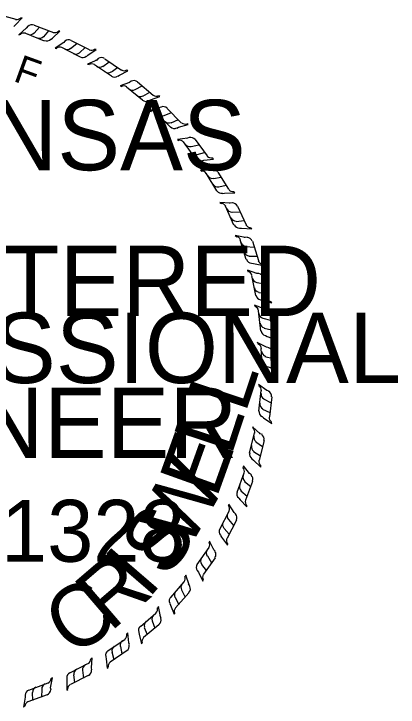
# Model space of a CAD drawing. Extents: x 208.7 to 242.8, y 328.9 to 350.7.
# Drawn here: x 234.537 to 235.56, y 330.334 to 332.182 of the extents above; entities that cross this region are included whole.
import ezdxf

# ---------------------------------------------------------------- set-up
doc = ezdxf.new("R2010")
doc.units = 0
doc.layers.add('Border 2660-Hwy18 - Stamp-ChrisC', color=7, linetype='Continuous')

msp = doc.modelspace()

# ---------------------------------------------------------------- linework, layer by layer
at = {"layer": 'Border 2660-Hwy18 - Stamp-ChrisC'}
for p, q in [((234.4894, 332.1816), (234.5419, 332.1674)), ((234.5404, 332.1516), (234.5584, 332.1711)), ((234.5584, 332.1711), (234.5554, 332.1704)), ((234.5367, 332.1479), (234.5404, 332.1516)), ((234.5734, 332.1486), (234.5704, 332.1441)), ((234.5907, 332.1516), (234.6417, 332.1321)), ((234.5907, 332.1299), (234.6049, 332.1464)), ((234.5704, 332.1441), (234.5494, 332.1261)), ((234.5494, 332.1261), (234.5547, 332.1276)), ((234.6184, 332.1089), (234.5682, 332.1291)), ((234.5704, 332.1441), (234.5689, 332.1426)), ((234.6162, 332.1201), (234.6297, 332.1366)), ((234.6394, 332.1171), (234.6589, 332.1359)), ((234.6589, 332.1359), (234.6552, 332.1351)), ((234.6357, 332.1141), (234.6394, 332.1171)), ((234.6724, 332.1089), (234.6694, 332.1051)), ((234.6889, 332.1104), (234.7369, 332.0864)), ((234.6694, 332.1051), (234.6462, 332.0901)), ((234.6462, 332.0901), (234.6514, 332.0894)), ((234.7137, 332.0661), (234.6642, 332.0916)), ((234.6694, 332.1051), (234.6664, 332.1036)), ((234.6874, 332.0894), (234.7039, 332.1029)), ((234.7114, 332.0774), (234.7264, 332.0916)), ((234.7302, 332.0684), (234.7339, 332.0714)), ((234.7339, 332.0714), (234.7557, 332.0864)), ((234.7557, 332.0864), (234.7519, 332.0879)), ((234.7572, 332.0586), (234.7324, 332.0474)), ((234.7572, 332.0586), (234.7549, 332.0579)), ((234.7609, 332.0624), (234.7572, 332.0586)), ((234.7737, 332.0414), (234.7902, 332.0534)), ((234.7789, 332.0616), (234.8232, 332.0316)), ((234.7324, 332.0474), (234.7369, 332.0466)), ((234.7969, 332.0159), (234.7512, 332.0459)), ((234.7962, 332.0271), (234.8127, 332.0384)), ((234.8134, 332.0159), (234.8179, 332.0181)), ((234.8179, 332.0181), (234.8404, 332.0301)), ((234.8404, 332.0301), (234.8374, 332.0324)), ((234.8449, 331.9986), (234.8194, 331.9896)), ((234.8449, 331.9986), (234.8427, 331.9979)), ((234.8487, 332.0024), (234.8449, 331.9986)), ((234.8659, 332.0001), (234.9072, 331.9649)), ((234.8194, 331.9896), (234.8239, 331.9881)), ((234.8794, 331.9514), (234.8367, 331.9866)), ((234.8592, 331.9799), (234.8779, 331.9896)), ((234.8802, 331.9626), (234.8982, 331.9731)), ((234.9004, 331.9521), (234.9252, 331.9611)), ((234.9252, 331.9611), (234.9222, 331.9634)), ((234.8959, 331.9499), (234.9004, 331.9521)), ((234.9237, 331.9311), (234.8982, 331.9244)), ((234.8982, 331.9244), (234.9027, 331.9214)), ((234.9237, 331.9311), (234.9214, 331.9296)), ((234.9282, 331.9334), (234.9237, 331.9311)), ((234.9447, 331.9296), (234.9822, 331.8914)), ((234.9537, 331.8801), (234.9147, 331.9199)), ((234.9372, 331.9109), (234.9559, 331.9184)), ((234.9552, 331.8914), (234.9747, 331.9004)), ((234.9747, 331.8794), (235.0009, 331.8869)), ((235.0009, 331.8869), (234.9979, 331.8884)), ((234.9702, 331.8771), (234.9747, 331.8794)), ((234.9987, 331.8501), (234.9724, 331.8471)), ((234.9987, 331.8501), (234.9964, 331.8494)), ((235.0032, 331.8524), (234.9987, 331.8501)), ((234.9724, 331.8471), (234.9762, 331.8441)), ((235.0212, 331.7954), (234.9882, 331.8404)), ((235.0084, 331.8284), (235.0287, 331.8329)), ((235.0189, 331.8464), (235.0512, 331.8029)), ((235.0242, 331.8066), (235.0444, 331.8126)), ((235.0422, 331.7916), (235.0684, 331.7946)), ((235.0684, 331.7946), (235.0654, 331.7976)), ((235.0369, 331.7901), (235.0422, 331.7916)), ((235.0602, 331.7654), (235.0332, 331.7654)), ((235.0332, 331.7654), (235.0369, 331.7616)), ((235.0774, 331.7099), (235.0489, 331.7571)), ((235.0602, 331.7654), (235.0572, 331.7661)), ((235.0647, 331.7676), (235.0602, 331.7654)), ((235.0797, 331.7601), (235.1082, 331.7144)), ((235.0677, 331.7429), (235.0887, 331.7466)), ((235.0819, 331.7204), (235.1022, 331.7249)), ((235.0932, 331.7031), (235.0977, 331.7039)), ((235.0977, 331.7039), (235.1247, 331.7046)), ((235.1247, 331.7046), (235.1217, 331.7076)), ((235.1127, 331.6769), (235.0849, 331.6791)), ((235.0849, 331.6791), (235.0894, 331.6761)), ((235.1224, 331.6184), (235.0999, 331.6694)), ((235.1127, 331.6769), (235.1097, 331.6769)), ((235.1187, 331.6784), (235.1127, 331.6769)), ((235.1322, 331.6694), (235.1547, 331.6199)), ((235.1172, 331.6529), (235.1397, 331.6544)), ((235.1284, 331.6281), (235.1502, 331.6311)), ((235.1382, 331.6109), (235.1427, 331.6109)), ((235.1427, 331.6109), (235.1704, 331.6086)), ((235.1704, 331.6086), (235.1674, 331.6116)), ((235.1524, 331.5854), (235.1254, 331.5914)), ((235.1254, 331.5914), (235.1299, 331.5876)), ((235.1554, 331.5269), (235.1389, 331.5794)), ((235.1524, 331.5854), (235.1502, 331.5861)), ((235.1584, 331.5869), (235.1524, 331.5854)), ((235.1719, 331.5756), (235.1877, 331.5246)), ((235.1539, 331.5614), (235.1764, 331.5599)), ((235.1622, 331.5359), (235.1839, 331.5359)), ((235.1697, 331.5171), (235.1749, 331.5164)), ((235.1749, 331.5164), (235.2012, 331.5111)), ((235.1839, 331.4901), (235.1584, 331.4991)), ((235.1584, 331.4991), (235.1607, 331.4946)), ((235.2012, 331.5111), (235.1989, 331.5141)), ((235.1809, 331.4309), (235.1704, 331.4849)), ((235.1839, 331.4901), (235.1817, 331.4909)), ((235.1892, 331.4901), (235.1839, 331.4901)), ((235.1832, 331.4661), (235.2042, 331.4624)), ((235.2012, 331.4766), (235.2117, 331.4241)), ((235.1884, 331.4391), (235.2094, 331.4369)), ((235.1937, 331.4196), (235.1982, 331.4181)), ((235.1982, 331.4181), (235.2237, 331.4114)), ((235.2237, 331.4114), (235.2222, 331.4136)), ((235.2027, 331.3956), (235.1772, 331.4054)), ((235.1772, 331.4054), (235.1794, 331.4016)), ((235.1944, 331.3364), (235.1877, 331.3904)), ((235.2027, 331.3956), (235.1997, 331.3956)), ((235.2079, 331.3949), (235.2027, 331.3956)), ((235.1997, 331.3709), (235.2199, 331.3656)), ((235.2177, 331.3806), (235.2244, 331.3266)), ((235.2027, 331.3439), (235.2229, 331.3394)), ((235.2064, 331.3244), (235.2109, 331.3221)), ((235.2109, 331.3221), (235.2357, 331.3131)), ((235.2357, 331.3131), (235.2349, 331.3161)), ((235.2094, 331.2936), (235.1847, 331.3056)), ((235.1847, 331.3056), (235.1884, 331.3019)), ((235.1982, 331.2351), (235.1952, 331.2899)), ((235.2094, 331.2936), (235.2072, 331.2944)), ((235.2162, 331.2921), (235.2094, 331.2936)), ((235.2259, 331.2779), (235.2297, 331.2239)), ((235.2049, 331.2689), (235.2274, 331.2636)), ((235.2072, 331.2426), (235.2282, 331.2366)), ((235.2094, 331.2224), (235.2139, 331.2201)), ((235.2139, 331.2201), (235.2387, 331.2096)), ((235.2387, 331.2096), (235.2372, 331.2126)), ((235.2102, 331.1781), (235.1877, 331.1939)), ((235.1877, 331.1939), (235.1907, 331.1894)), ((235.1884, 331.1234), (235.1952, 331.1781)), ((235.2102, 331.1781), (235.2079, 331.1796)), ((235.2162, 331.1766), (235.2102, 331.1781)), ((235.2012, 331.1556), (235.2214, 331.1451)), ((235.2237, 331.1609), (235.2169, 331.1076)), ((235.1982, 331.1286), (235.2184, 331.1196)), ((235.1974, 331.1084), (235.2012, 331.1054)), ((235.2012, 331.1054), (235.2237, 331.0904)), ((235.2237, 331.0904), (235.2229, 331.0941)), ((235.1922, 331.0626), (235.1719, 331.0814)), ((235.1719, 331.0814), (235.1742, 331.0769)), ((235.1637, 331.0109), (235.1772, 331.0649)), ((235.1922, 331.0626), (235.1907, 331.0649)), ((235.1982, 331.0604), (235.1922, 331.0626)), ((235.1809, 331.0416), (235.1989, 331.0289)), ((235.2034, 331.0446), (235.1899, 330.9921)), ((235.1742, 331.0154), (235.1929, 331.0041)), ((235.1704, 330.9959), (235.1749, 330.9921)), ((235.1749, 330.9921), (235.1944, 330.9741)), ((235.1479, 330.9771), (235.1472, 330.9726)), ((235.1644, 330.9569), (235.1479, 330.9771)), ((235.1944, 330.9741), (235.1944, 330.9779)), ((235.1314, 330.9074), (235.1502, 330.9584)), ((235.1644, 330.9569), (235.1629, 330.9576)), ((235.1689, 330.9531), (235.1644, 330.9569)), ((235.1509, 330.9359), (235.1674, 330.9224)), ((235.1719, 330.9359), (235.1532, 330.8856)), ((235.1412, 330.9104), (235.1577, 330.8969)), ((235.1359, 330.8909), (235.1389, 330.8871)), ((235.1089, 330.8751), (235.1082, 330.8706)), ((235.1232, 330.8526), (235.1089, 330.8751)), ((235.1389, 330.8871), (235.1569, 330.8684)), ((235.1569, 330.8684), (235.1569, 330.8714)), ((235.0849, 330.8084), (235.1104, 330.8579)), ((235.1232, 330.8526), (235.1224, 330.8549)), ((235.1277, 330.8489), (235.1232, 330.8526)), ((235.1082, 330.8346), (235.1217, 330.8181)), ((235.1292, 330.8324), (235.1044, 330.7844)), ((235.0962, 330.8106), (235.1097, 330.7956)), ((235.0872, 330.7919), (235.0894, 330.7874)), ((235.0894, 330.7874), (235.1052, 330.7664)), ((235.0249, 330.7146), (235.0564, 330.7596)), ((235.0579, 330.7769), (235.0564, 330.7724)), ((235.0692, 330.7536), (235.0579, 330.7769)), ((235.1052, 330.7664), (235.1059, 330.7701)), ((235.0692, 330.7536), (235.0677, 330.7559)), ((235.0729, 330.7499), (235.0692, 330.7536)), ((235.0722, 330.7326), (235.0414, 330.6884)), ((235.0519, 330.7371), (235.0632, 330.7191)), ((235.0362, 330.7146), (235.0482, 330.6981)), ((234.9942, 330.6861), (234.9927, 330.6816)), ((235.0032, 330.6606), (234.9942, 330.6861)), ((235.0249, 330.6981), (235.0279, 330.6936)), ((235.0279, 330.6936), (235.0399, 330.6696)), ((234.9544, 330.6269), (234.9904, 330.6681)), ((235.0399, 330.6696), (235.0407, 330.6734)), ((235.0032, 330.6606), (235.0017, 330.6629)), ((235.0054, 330.6561), (235.0032, 330.6606)), ((235.0024, 330.6389), (234.9672, 330.5991)), ((234.9829, 330.6471), (234.9927, 330.6276)), ((234.9657, 330.6261), (234.9754, 330.6081)), ((234.9214, 330.6021), (234.9192, 330.5984)), ((234.9267, 330.5759), (234.9214, 330.6021)), ((234.9522, 330.6104), (234.9537, 330.6059)), ((234.9537, 330.6059), (234.9634, 330.5819)), ((234.8734, 330.5496), (234.9147, 330.5849)), ((234.9267, 330.5759), (234.9259, 330.5781)), ((234.9289, 330.5706), (234.9267, 330.5759)), ((234.9634, 330.5819), (234.9649, 330.5841)), ((234.9049, 330.5646), (234.9117, 330.5444)), ((234.9229, 330.5541), (234.8817, 330.5196)), ((234.8839, 330.5466), (234.8914, 330.5279)), ((234.8404, 330.5324), (234.8367, 330.5286)), ((234.8427, 330.5054), (234.8404, 330.5324)), ((234.8689, 330.5331), (234.8704, 330.5286)), ((234.8704, 330.5286), (234.8764, 330.5031)), ((234.7872, 330.4844), (234.8329, 330.5159)), ((234.8427, 330.5054), (234.8427, 330.5084)), ((234.8442, 330.5009), (234.8427, 330.5054)), ((234.8764, 330.5031), (234.8779, 330.5054)), ((234.8382, 330.4851), (234.7932, 330.4544)), ((234.8202, 330.4956), (234.8239, 330.4761)), ((234.7452, 330.4656), (234.7414, 330.4626)), ((234.7437, 330.4394), (234.7452, 330.4656)), ((234.7819, 330.4686), (234.7827, 330.4634)), ((234.7977, 330.4814), (234.8029, 330.4611)), ((234.6859, 330.4259), (234.7339, 330.4506)), ((234.7827, 330.4634), (234.7849, 330.4379)), ((234.7197, 330.4326), (234.7219, 330.4116)), ((234.7437, 330.4394), (234.7429, 330.4416)), ((234.7444, 330.4334), (234.7437, 330.4394)), ((234.7849, 330.4379), (234.7879, 330.4401)), ((234.6342, 330.3861), (234.6394, 330.4124)), ((234.6394, 330.4124), (234.6357, 330.4094)), ((234.6777, 330.4109), (234.6777, 330.4056)), ((234.7347, 330.4191), (234.6874, 330.3944)), ((234.6957, 330.4206), (234.6979, 330.3996)), ((234.5764, 330.3794), (234.6282, 330.3989)), ((234.6777, 330.4056), (234.6777, 330.3794)), ((234.5854, 330.3734), (234.5862, 330.3524)), ((234.6109, 330.3824), (234.6102, 330.3614)), ((234.6342, 330.3861), (234.6349, 330.3891)), ((234.6357, 330.3809), (234.6342, 330.3861)), ((234.6777, 330.3794), (234.6799, 330.3816)), ((234.5667, 330.3606), (234.5622, 330.3344)), ((234.5667, 330.3659), (234.5667, 330.3606)), ((234.6252, 330.3674), (234.5742, 330.3486)), ((234.5622, 330.3344), (234.5652, 330.3366))]:
    msp.add_line(p, q, dxfattribs=at)
for centre, start, end in [((234.5442, 332.1814), 258.2517, 317.0395), ((234.5851, 332.138), 69.0955, 137.4695), ((234.5637, 332.1157), 73.3563, 132.1441), ((234.58, 332.1409), 249.0955, 317.4695), ((234.6453, 332.1464), 253.3563, 312.1441), ((234.6047, 332.1313), 249.0955, 317.4695), ((234.6239, 332.1241), 249.0955, 317.4695), ((234.6825, 332.0978), 63.0708, 131.4448), ((234.6589, 332.0779), 67.3316, 126.1194), ((234.6778, 332.1012), 243.0708, 311.4448), ((234.7013, 332.0891), 243.0708, 311.4448), ((234.7432, 332.0998), 247.3316, 306.1194), ((234.7196, 332.0799), 243.0708, 311.4448), ((234.7698, 332.0503), 56.1736, 124.5476), ((234.7439, 332.0334), 60.4344, 119.2222), ((234.7655, 332.0542), 236.1736, 304.5476), ((234.7874, 332.0394), 236.1736, 304.5476), ((234.8045, 332.028), 236.1736, 304.5476), ((234.8303, 332.045), 240.4344, 299.2222), ((234.8564, 331.9889), 50.1902, 118.5642), ((234.8289, 331.9747), 54.451, 113.2388), ((234.8525, 331.9932), 230.1902, 298.5642), ((234.8728, 331.9762), 230.1902, 298.5642), ((234.916, 331.9773), 234.451, 293.2388), ((234.8886, 331.9631), 230.1902, 298.5642), ((234.9058, 331.9081), 49.2262, 108.0141), ((234.9344, 331.9197), 44.9655, 113.3394), ((234.931, 331.9244), 224.9655, 293.3394), ((234.9496, 331.9056), 224.9655, 293.3394), ((234.9928, 331.9028), 229.2262, 288.0141), ((234.9641, 331.8911), 224.9655, 293.3394), ((235.0075, 331.8376), 36.6897, 105.0637), ((234.9775, 331.8302), 40.9505, 99.7383), ((235.0048, 331.8427), 216.6897, 285.0637), ((235.0205, 331.8214), 216.6897, 285.0637), ((235.0328, 331.805), 216.6897, 285.0637), ((235.0628, 331.8124), 220.9505, 279.7383), ((235.037, 331.7479), 36.0034, 94.7913), ((235.0675, 331.7527), 31.7427, 100.1166), ((235.0653, 331.758), 211.7427, 280.1166), ((235.0791, 331.7355), 211.7427, 280.1166), ((235.0899, 331.7181), 211.7427, 280.1166), ((235.1205, 331.7228), 216.0034, 274.7913), ((235.0876, 331.6618), 29.1451, 87.9329), ((235.1185, 331.6629), 24.8843, 93.2583), ((235.1169, 331.6684), 204.8843, 273.2583), ((235.1279, 331.6444), 204.8843, 273.2583), ((235.1366, 331.6258), 204.8843, 273.2583), ((235.1675, 331.6269), 209.1451, 267.9329), ((235.1261, 331.5738), 22.0938, 80.8817), ((235.156, 331.5768), 197.8331, 266.207), ((235.1569, 331.5711), 17.8331, 86.207), ((235.164, 331.5516), 197.8331, 266.207), ((235.1703, 331.5321), 197.8331, 266.207), ((235.2011, 331.5294), 202.0938, 260.8817), ((235.1562, 331.4809), 15.7912, 74.579), ((235.1865, 331.4749), 11.5304, 79.9044), ((235.1862, 331.4806), 191.5304, 259.9044), ((235.1914, 331.4547), 191.5304, 259.9044), ((235.1956, 331.4346), 191.5304, 259.9044), ((235.2259, 331.4285), 195.7912, 254.579), ((235.1737, 331.3878), 11.4348, 70.2227), ((235.2035, 331.3795), 7.174, 75.548), ((235.2036, 331.3852), 187.174, 255.548), ((235.2068, 331.359), 187.174, 255.548), ((235.2094, 331.3386), 187.174, 255.548), ((235.2392, 331.3303), 191.4348, 250.2227), ((235.1811, 331.2881), 8.033, 66.8208), ((235.2108, 331.2837), 183.7722, 252.1462), ((235.2103, 331.278), 3.7722, 72.1462), ((235.2125, 331.2574), 183.7722, 252.1462), ((235.2139, 331.2369), 183.7722, 252.1462), ((235.2431, 331.2268), 188.033, 246.8208), ((235.181, 331.1782), 357.57, 56.3579), ((235.2094, 331.1685), 173.3093, 241.6832), ((235.2079, 331.163), 353.3093, 61.6832), ((235.2062, 331.1423), 173.3093, 241.6832), ((235.2039, 331.1219), 173.3093, 241.6832), ((235.2308, 331.1067), 177.57, 236.3579), ((235.1632, 331.0668), 350.445, 49.2329), ((235.1902, 331.0537), 166.1842, 234.5582), ((235.188, 331.0483), 346.1842, 54.5582), ((235.1838, 331.028), 166.1842, 234.5582), ((235.1789, 331.0081), 166.1842, 234.5582), ((235.2037, 330.9896), 170.445, 229.2329), ((235.1358, 330.9627), 344.1611, 42.9489), ((235.1612, 330.9468), 159.9003, 228.2743), ((235.1584, 330.9417), 339.9003, 48.2743), ((235.152, 330.922), 159.9003, 228.2743), ((235.145, 330.9027), 159.9003, 228.2743), ((235.096, 330.863), 337.1149, 35.9028), ((235.1676, 330.8816), 164.1611, 222.9489), ((235.1193, 330.8441), 152.8541, 221.2281), ((235.1159, 330.8394), 332.8541, 41.2281), ((235.1071, 330.8206), 152.8541, 221.2281), ((235.0978, 330.8023), 152.8541, 221.2281), ((235.1177, 330.7786), 157.1149, 215.9028), ((235.0432, 330.7671), 329.7262, 28.514), ((235.0638, 330.7453), 145.4654, 213.8394), ((235.0598, 330.7411), 325.4654, 33.8394), ((235.0487, 330.7236), 145.4654, 213.8394), ((235.0371, 330.7066), 145.4654, 213.8394), ((235.0538, 330.6806), 149.7262, 208.514), ((234.9784, 330.6773), 322.7822, 21.57), ((234.9962, 330.6532), 138.5214, 206.8953), ((234.9918, 330.6495), 318.5214, 26.8953), ((234.9786, 330.6334), 138.5214, 206.8953), ((234.9651, 330.618), 138.5214, 206.8953), ((234.9044, 330.5955), 314.7826, 13.5704), ((234.9785, 330.5902), 142.7822, 201.57), ((234.9187, 330.5691), 130.5218, 198.8958), ((234.8986, 330.552), 130.5218, 198.8958), ((234.9138, 330.566), 310.5218, 18.8958), ((234.883, 330.5386), 130.5218, 198.8958), ((234.8228, 330.5273), 308.9134, 7.7012), ((234.8924, 330.5092), 134.7826, 193.5704), ((234.8343, 330.4996), 124.6526, 193.0266), ((234.8292, 330.4971), 304.6526, 13.0266), ((234.7957, 330.4729), 124.6526, 193.0266), ((234.8125, 330.4846), 124.6526, 193.0266), ((234.7342, 330.4341), 116.8386, 185.2126), ((234.7266, 330.4631), 301.0994, 359.8872), ((234.802, 330.4427), 128.9134, 187.7013), ((234.7106, 330.4222), 116.8386, 185.2126), ((234.7287, 330.4323), 296.8386, 5.2126), ((234.6211, 330.4121), 294.7331, 353.521), ((234.6923, 330.4129), 116.8386, 185.2126), ((234.6255, 330.3824), 110.4724, 178.8463), ((234.6944, 330.3821), 121.0994, 179.8872), ((234.5815, 330.366), 110.4724, 178.8463), ((234.6007, 330.3733), 110.4724, 178.8463), ((234.6198, 330.3812), 290.4724, 358.8463), ((234.5802, 330.3351), 114.7331, 173.521)]:
    msp.add_arc(centre, 0.0148, start, end, dxfattribs=at)

# ---------------------------------------------------------------- texts
for s, height, rotation, p in [('F', 0.075, 340.0707, (234.5324, 332.0034)), ('L', 0.1642, 71.6828, (235.1525, 331.1146)), ('L', 0.1642, 71.6828, (235.1148, 331.0008)), ('E', 0.1642, 70.3031, (235.0755, 330.8875)), ('W', 0.1642, 60.0948, (234.9995, 330.7494)), ('S', 0.1642, 53.9956, (234.9429, 330.6741)), ('I', 0.1642, 49.2381, (234.8933, 330.6198)), ('R', 0.1642, 40.6231, (234.7928, 330.5326)), ('C', 0.1642, 32.5951, (234.6883, 330.4658))]:
    msp.add_text(s, height=height, rotation=rotation, dxfattribs=at).set_placement(p)
for s, height, p in [('ARKANSAS', 0.1875, (233.7884, 331.7649)), ('REGISTERED', 0.1875, (233.7247, 331.3764)), ('PROFESSIONAL', 0.187497, (233.6174, 331.1979)), ('ENGINEER', 0.1875, (233.8222, 330.9984)), ('No. 11328', 0.165, (233.9753, 330.7217))]:
    msp.add_text(s, height=height, dxfattribs=at).set_placement(p)

doc.saveas('drawing.dxf')
